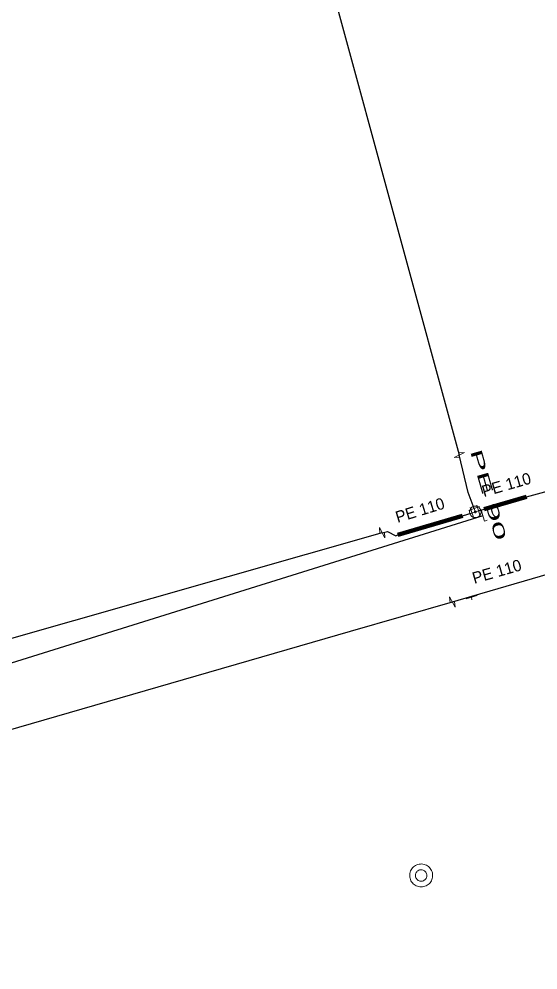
# Model space of a CAD drawing. Extents: x -690254 to -689100, y -975264 to -974703.
# Drawn here: x -689692.3 to -689647.1, y -975075.2 to -974992.3 of the extents above; entities that cross this region are included whole.
import ezdxf

# ---------------------------------------------------------------- set-up
doc = ezdxf.new("R2010")
doc.units = 0
doc.header["$LTSCALE"] = 0.4
for name, color, linetype, lineweight in [('1', 7, 'Continuous', 13), ('13', 7, 'Continuous', 13), ('14', 7, 'Continuous', 13), ('17', 7, 'Continuous', 25), ('22', 7, 'Continuous', 13), ('3', 7, 'Continuous', 106), ('34', 7, 'Continuous', 13), ('47', 7, 'Continuous', 13)]:
    doc.layers.add(name, color=color, linetype=linetype, lineweight=lineweight)

msp = doc.modelspace()

# ---------------------------------------------------------------- linework, layer by layer
at = {"layer": '13'}
msp.add_line((-689652.865, -975042.715), (-689652.835, -975042.954), dxfattribs=at)
at = {"layer": '14'}
for p, q in [((-689652.831, -975035.35), (-689652.544, -975035.272)), ((-689652.544, -975035.272), (-689652.638, -975034.978)), ((-689652.544, -975035.272), (-689652.269, -975035.174)), ((-689652.008, -975035.146), (-689651.896, -975035.605)), ((-689652.884, -975042.649), (-689652.865, -975042.715))]:
    msp.add_line(p, q, dxfattribs=at)
at = {"layer": '17'}
for p, q in [((-689679.393, -974936.834), (-689653.94, -975030.302)), ((-689660.67, -975037.094), (-689736.277, -975058.649))]:
    msp.add_line(p, q, dxfattribs=at)
for points in [[(-689652.638, -975034.978), (-689653.179, -975033.581), (-689653.94, -975030.302)], [(-689652.269, -975035.174), (-689651.761, -975035.033), (-689648.094, -975033.951), (-689645.011, -975033.107)], [(-689651.896, -975035.605), (-689702.719, -975051.484), (-689800.052, -975078.399), (-689860.597, -975095.177), (-689913.514, -975110.178), (-689937.55, -975117.079), (-689948.793, -975119.833), (-689957.109, -975122.39), (-689986.109, -975129.956), (-690002.122, -975134.99), (-690005.949, -975136.193), (-690003.879, -975142.529), (-690036.781, -975151.448), (-690069.227, -975161.229), (-690080.424, -975165.129), (-690111.773, -975174.27), (-690115.204, -975175.288), (-690118.142, -975167.265)], [(-689660.67, -975037.094), (-689660.212, -975036.98), (-689659.484, -975037.35), (-689659.307, -975037.261), (-689653.669, -975035.627), (-689652.831, -975035.35)], [(-689644.419, -975040.174), (-689644.603, -975040.227), (-689652.884, -975042.649), (-689654.548, -975043.14)], [(-689654.548, -975043.14), (-689663.456, -975045.689), (-689770.531, -975076.689), (-689789.368, -975082.372), (-689795.659, -975083.946), (-689875.347, -975106.869), (-689899.317, -975114.153), (-689955.443, -975128.986), (-689982.052, -975137.931), (-690059.236, -975159.265)]]:
    msp.add_lwpolyline(points, dxfattribs=at)
at = {"layer": '22'}
for points in [[(-689656.263, -975066.977), (-689656.269, -975066.868), (-689656.287, -975066.76), (-689656.317, -975066.654), (-689656.357, -975066.553), (-689656.409, -975066.456), (-689656.471, -975066.366), (-689656.543, -975066.283), (-689656.623, -975066.209), (-689656.711, -975066.143), (-689656.805, -975066.088), (-689656.905, -975066.043), (-689657.01, -975066.01), (-689657.117, -975065.988), (-689657.226, -975065.978), (-689657.336, -975065.98), (-689657.444, -975065.994), (-689657.551, -975066.019), (-689657.654, -975066.056), (-689657.752, -975066.105), (-689657.844, -975066.163), (-689657.93, -975066.232), (-689658.007, -975066.309), (-689658.076, -975066.395), (-689658.135, -975066.487), (-689658.183, -975066.585), (-689658.22, -975066.688), (-689658.246, -975066.795), (-689658.26, -975066.903), (-689658.262, -975067.013), (-689658.252, -975067.122), (-689658.231, -975067.229), (-689658.197, -975067.333), (-689658.153, -975067.433), (-689658.098, -975067.528), (-689658.032, -975067.616), (-689657.958, -975067.696), (-689657.875, -975067.768), (-689657.785, -975067.83), (-689657.689, -975067.882), (-689657.587, -975067.923), (-689657.482, -975067.953), (-689657.374, -975067.971), (-689657.264, -975067.977), (-689657.155, -975067.971), (-689657.047, -975067.953), (-689656.942, -975067.924), (-689656.84, -975067.883), (-689656.743, -975067.831), (-689656.653, -975067.769), (-689656.57, -975067.698), (-689656.495, -975067.618), (-689656.43, -975067.53), (-689656.374, -975067.436), (-689656.33, -975067.336), (-689656.296, -975067.232), (-689656.274, -975067.124), (-689656.264, -975067.015)], [(-689656.763, -975066.977), (-689656.769, -975066.9), (-689656.787, -975066.825), (-689656.816, -975066.753), (-689656.856, -975066.687), (-689656.906, -975066.627), (-689656.964, -975066.576), (-689657.029, -975066.535), (-689657.1, -975066.504), (-689657.175, -975066.485), (-689657.252, -975066.477), (-689657.33, -975066.481), (-689657.405, -975066.498), (-689657.478, -975066.525), (-689657.545, -975066.564), (-689657.605, -975066.612), (-689657.657, -975066.67), (-689657.7, -975066.734), (-689657.732, -975066.804), (-689657.753, -975066.879), (-689657.763, -975066.956), (-689657.76, -975067.033), (-689657.745, -975067.109), (-689657.719, -975067.182), (-689657.682, -975067.25), (-689657.635, -975067.311), (-689657.579, -975067.365), (-689657.515, -975067.409), (-689657.445, -975067.443), (-689657.371, -975067.465), (-689657.295, -975067.476), (-689657.217, -975067.475), (-689657.141, -975067.462), (-689657.068, -975067.437), (-689656.999, -975067.402), (-689656.937, -975067.356), (-689656.882, -975067.301), (-689656.837, -975067.238), (-689656.801, -975067.169), (-689656.777, -975067.096), (-689656.765, -975067.019)]]:
    msp.add_lwpolyline(points, close=True, dxfattribs=at)
at = {"layer": '3'}
for p, q in [((-689651.761, -975035.033), (-689648.094, -975033.951)), ((-689659.307, -975037.261), (-689653.669, -975035.627))]:
    msp.add_line(p, q, dxfattribs=at)
at = {"layer": '3', "lineweight": 100}
for p, q in [((-689651.761, -975035.033), (-689648.094, -975033.951)), ((-689659.307, -975037.261), (-689653.669, -975035.627))]:
    msp.add_line(p, q, dxfattribs=at)
at = {"layer": '34'}
for p, q in [((-689653.104, -975035.158), (-689652.171, -975034.798)), ((-689652.403, -975034.692), (-689652.135, -975035.655)), ((-689652.989, -975034.875), (-689652.673, -975035.824)), ((-689652.385, -975042.574), (-689653.345, -975042.854))]:
    msp.add_line(p, q, dxfattribs=at)
at = {"layer": '47'}
for p, q in [((-689653.483, -975030.076), (-689653.992, -975030.108)), ((-689660.438, -975037.547), (-689660.476, -975037.038)), ((-689654.312, -975043.591), (-689654.355, -975043.083))]:
    msp.add_line(p, q, dxfattribs=at)
for points in [[(-689653.483, -975030.076), (-689654.396, -975030.527), (-689653.887, -975030.495)], [(-689651.507, -975036.003), (-689651.748, -975036.078), (-689652.043, -975035.131), (-689651.803, -975035.056)], [(-689660.438, -975037.547), (-689660.901, -975036.64), (-689660.863, -975037.149)], [(-689654.312, -975043.591), (-689654.783, -975042.688), (-689654.74, -975043.196)]]:
    msp.add_lwpolyline(points, dxfattribs=at)
for points in [[(-689652.044, -975035.272), (-689652.047, -975035.22), (-689652.055, -975035.168), (-689652.069, -975035.118), (-689652.087, -975035.069), (-689652.111, -975035.022), (-689652.14, -975034.978), (-689652.173, -975034.938), (-689652.21, -975034.901), (-689652.25, -975034.868), (-689652.294, -975034.839), (-689652.341, -975034.815), (-689652.39, -975034.797), (-689652.44, -975034.783), (-689652.492, -975034.775), (-689652.544, -975034.772), (-689652.596, -975034.775), (-689652.648, -975034.783), (-689652.699, -975034.797), (-689652.747, -975034.815), (-689652.794, -975034.839), (-689652.838, -975034.868), (-689652.879, -975034.901), (-689652.916, -975034.938), (-689652.949, -975034.978), (-689652.977, -975035.022), (-689653.001, -975035.069), (-689653.02, -975035.118), (-689653.032, -975035.168), (-689653.041, -975035.22), (-689653.044, -975035.272), (-689653.041, -975035.324), (-689653.032, -975035.376), (-689653.02, -975035.427), (-689653.001, -975035.475), (-689652.977, -975035.522), (-689652.949, -975035.566), (-689652.916, -975035.607), (-689652.879, -975035.644), (-689652.838, -975035.677), (-689652.794, -975035.705), (-689652.747, -975035.729), (-689652.699, -975035.748), (-689652.648, -975035.761), (-689652.596, -975035.769), (-689652.544, -975035.772), (-689652.492, -975035.769), (-689652.44, -975035.761), (-689652.39, -975035.748), (-689652.341, -975035.729), (-689652.294, -975035.705), (-689652.25, -975035.677), (-689652.21, -975035.644), (-689652.173, -975035.607), (-689652.14, -975035.566), (-689652.111, -975035.522), (-689652.087, -975035.475), (-689652.069, -975035.427), (-689652.055, -975035.376), (-689652.047, -975035.324)], [(-689652.462, -975035.272), (-689652.462, -975035.263), (-689652.464, -975035.255), (-689652.466, -975035.247), (-689652.469, -975035.239), (-689652.473, -975035.231), (-689652.478, -975035.224), (-689652.483, -975035.217), (-689652.489, -975035.211), (-689652.496, -975035.206), (-689652.503, -975035.201), (-689652.511, -975035.197), (-689652.519, -975035.194), (-689652.527, -975035.192), (-689652.535, -975035.19), (-689652.544, -975035.19), (-689652.553, -975035.19), (-689652.561, -975035.192), (-689652.569, -975035.194), (-689652.577, -975035.197), (-689652.585, -975035.201), (-689652.592, -975035.206), (-689652.599, -975035.211), (-689652.605, -975035.217), (-689652.611, -975035.224), (-689652.615, -975035.231), (-689652.619, -975035.239), (-689652.622, -975035.247), (-689652.624, -975035.255), (-689652.626, -975035.263), (-689652.626, -975035.272), (-689652.626, -975035.281), (-689652.624, -975035.289), (-689652.622, -975035.297), (-689652.619, -975035.305), (-689652.615, -975035.313), (-689652.611, -975035.32), (-689652.605, -975035.327), (-689652.599, -975035.333), (-689652.592, -975035.339), (-689652.585, -975035.343), (-689652.577, -975035.347), (-689652.569, -975035.35), (-689652.561, -975035.352), (-689652.553, -975035.354), (-689652.544, -975035.354), (-689652.535, -975035.354), (-689652.527, -975035.352), (-689652.519, -975035.35), (-689652.511, -975035.347), (-689652.503, -975035.343), (-689652.496, -975035.339), (-689652.489, -975035.333), (-689652.483, -975035.327), (-689652.478, -975035.32), (-689652.473, -975035.313), (-689652.469, -975035.305), (-689652.466, -975035.297), (-689652.464, -975035.289), (-689652.462, -975035.281)]]:
    msp.add_lwpolyline(points, close=True, dxfattribs=at)

# ---------------------------------------------------------------- texts
at = {"layer": '1', "width": 2.25}
msp.add_text('PE 90 ', height=1, rotation=286, dxfattribs=at).set_placement((-689653.009, -975029.967))
at = {"layer": '1'}
for rotation, p in [(16, (-689651.804, -975033.982)), (17, (-689659.323, -975036.236)), (16, (-689652.64, -975041.551))]:
    msp.add_text('PE 110', height=1, rotation=rotation, dxfattribs=at).set_placement(p)

doc.saveas('drawing.dxf')
